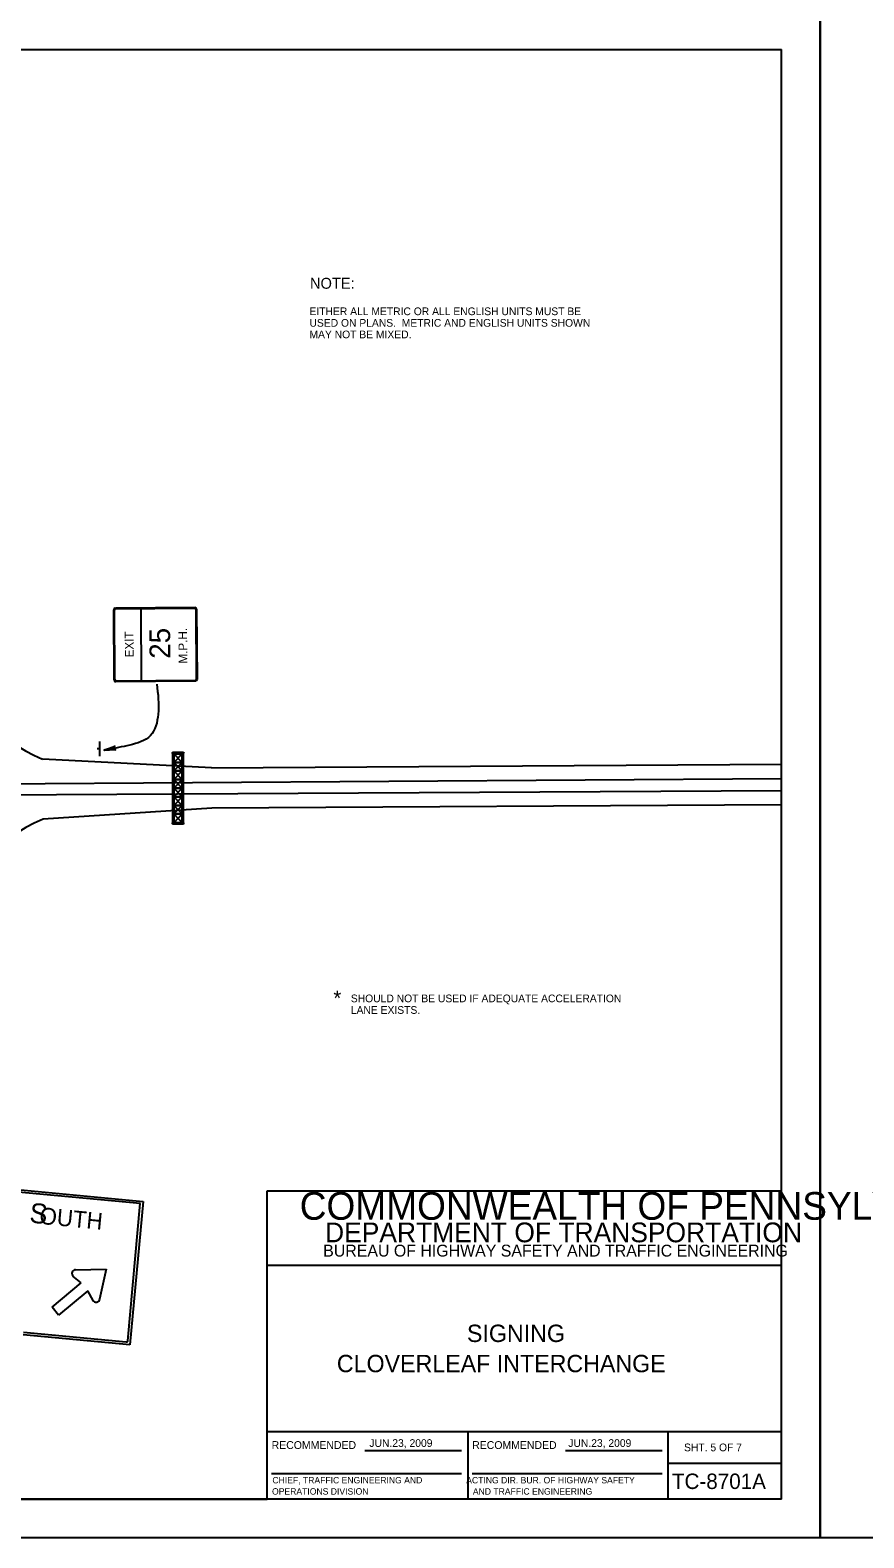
# Model space of a CAD drawing. Extents: x 640994 to 644422, y 298458 to 299646.
# Drawn here: x 641528 to 641852, y 298458 to 299044 of the extents above; entities that cross this region are included whole.
import ezdxf

# ---------------------------------------------------------------- set-up
doc = ezdxf.new("R2010")
doc.units = 0
for name, color, linetype in [('1', 7, 'Continuous'), ('2', 7, 'Continuous'), ('PLT-BNDY', 7, 'Continuous'), ('XCS-GRID-MIN', 7, 'Continuous')]:
    doc.layers.add(name, color=color, linetype=linetype)

msp = doc.modelspace()

# ---------------------------------------------------------------- linework, layer by layer
at = {"layer": '1'}
for p, q in [((641034.31, 299036.63), (641820.31, 299036.63)), ((641820.31, 298472.63), (641820.31, 299036.63)), ((641620.31, 298472.63), (641620.31, 298592.63)), ((641620.31, 298592.63), (641820.31, 298592.63)), ((641820.31, 298563.63), (641620.31, 298563.63)), ((641620.31, 298499), (641820.31, 298499)), ((641698.31, 298499), (641698.31, 298472.63)), ((641776.19, 298472.63), (641776.19, 298499)), ((641658.24, 298491.57), (641695.87, 298491.57)), ((641736.24, 298491.57), (641773.87, 298491.57)), ((641621.99, 298482.68), (641695.87, 298482.68)), ((641699.99, 298482.68), (641773.87, 298482.68)), ((641776.19, 298486.63), (641820.31, 298486.63)), ((641820.31, 298472.63), (641034.31, 298472.63)), ((641034.31, 298472.63), (641620.31, 298472.63))]:
    msp.add_line(p, q, dxfattribs=at)
at = {"layer": '2'}
for p, q in [((641560.69, 298791.38), (641560.56, 298818.63)), ((641560.94, 298791.5), (641560.81, 298818.38)), ((641561.19, 298819.38), (641592.19, 298819.63)), ((641561.31, 298819), (641591.94, 298819.25)), ((641571.31, 298791), (641571.19, 298819.13)), ((641592.56, 298818.63), (641592.69, 298791.75)), ((641592.81, 298818.88), (641593.06, 298791.5)), ((641592.44, 298790.88), (641561.31, 298790.63)), ((641592.19, 298791.13), (641561.56, 298790.88)), ((641555.06, 298764.5), (641554.06, 298764.5)), ((641555.06, 298767.38), (641555.06, 298761.75)), ((641598.56, 298757.13), (641532.94, 298760.5)), ((641583.94, 298762.63), (641587.19, 298759.25)), ((641587.19, 298762.63), (641583.94, 298759.25)), ((641583.94, 298759.25), (641587.19, 298756)), ((641587.19, 298759.25), (641583.94, 298756)), ((641598.56, 298757.13), (641820.31, 298758.53)), ((641820.31, 298752.92), (641403.56, 298750.13)), ((641583.94, 298756), (641587.19, 298752.63)), ((641587.19, 298756), (641583.94, 298752.63)), ((641583.94, 298752.63), (641587.19, 298749.25)), ((641587.19, 298752.63), (641583.94, 298749.25)), ((641403.06, 298746), (641820.31, 298748.39)), ((641583.94, 298749.25), (641587.19, 298745.88)), ((641587.19, 298749.25), (641583.94, 298745.88)), ((641583.94, 298745.88), (641587.19, 298742.5)), ((641587.19, 298745.88), (641583.94, 298742.5)), ((641598.69, 298741.5), (641533.06, 298737.25)), ((641583.94, 298742.5), (641587.19, 298739.25)), ((641587.19, 298742.5), (641583.94, 298739.25)), ((641820.31, 298742.77), (641598.69, 298741.5)), ((641583.94, 298739.25), (641587.19, 298735.75)), ((641587.19, 298739.25), (641583.94, 298735.75)), ((641587.19, 298735.75), (641587.19, 298739.25)), ((641482.95, 298596.91), (641572.07, 298588.42)), ((641566.07, 298534.29), (641570.89, 298587.75)), ((641572.07, 298588.42), (641566.82, 298532.67)), ((641547.95, 298556.79), (641544.7, 298559.42)), ((641545.7, 298561.92), (641557.57, 298562.17)), ((641557.57, 298562.17), (641555.07, 298550.42)), ((641536.57, 298547.42), (641547.95, 298556.79)), ((641550.45, 298553.67), (641539.07, 298544.29)), ((641552.57, 298549.92), (641550.45, 298553.67)), ((641539.07, 298544.29), (641536.57, 298547.42)), ((641566.82, 298532.67), (641525.37, 298536.61)), ((641525.47, 298537.63), (641565.45, 298533.92))]:
    msp.add_line(p, q, dxfattribs=at)
for points in [[(641561.03, 298764.34), (641560.78, 298764.59), (641556.9, 298764.09), (641561.03, 298764.34), (641561.28, 298764.21), (641556.9, 298764.09), (641560.78, 298764.96), (641560.78, 298765.21), (641556.9, 298764.09), (641561.03, 298765.59), (641560.78, 298765.21)], [(641587.19, 298763.13), (641583.94, 298763.13)], [(641583.44, 298762.63), (641583.44, 298735.75)], [(641583.94, 298735.75), (641587.19, 298735.75), (641587.19, 298762.63), (641583.94, 298762.63), (641583.94, 298735.75)], [(641587.69, 298735.75), (641587.69, 298762.63)], [(641583.94, 298735.38), (641587.19, 298735.38)], [(641570.89, 298587.75), (641484.32, 298595.67)]]:
    msp.add_lwpolyline(points, dxfattribs=at)
for points in [[(641583.94, 298759.25), (641583.94, 298762.63), (641587.19, 298762.63), (641587.19, 298759.25)], [(641583.94, 298756), (641583.94, 298759.25), (641587.19, 298759.25), (641587.19, 298756)], [(641583.94, 298752.63), (641583.94, 298756), (641587.19, 298756), (641587.19, 298752.63)], [(641583.94, 298749.25), (641583.94, 298752.63), (641587.19, 298752.63), (641587.19, 298749.25)], [(641583.94, 298745.88), (641583.94, 298749.25), (641587.19, 298749.25), (641587.19, 298745.88)], [(641583.94, 298742.5), (641583.94, 298745.88), (641587.19, 298745.88), (641587.19, 298742.5)], [(641583.94, 298739.25), (641583.94, 298742.5), (641587.19, 298742.5), (641587.19, 298739.25)], [(641583.94, 298735.75), (641583.94, 298739.25), (641587.19, 298739.25), (641587.19, 298735.75)]]:
    msp.add_lwpolyline(points, close=True, dxfattribs=at)
for centre in [(641583.7, 298762.91), (641587.48, 298762.91), (641583.7, 298735.61), (641587.48, 298735.61)]:
    msp.add_circle(centre, 0.301, dxfattribs=at)
for centre, radius, start, end in [((641555.3, 298815.87), 59.66, 191.54204, 247.96006), ((641556.17, 298682.23), 59.66, 112.7883, 169.20632), ((641570.38, 298587.12), 0.528, 354.14399, 84.50768), ((641545.72, 298560.49), 1.4, 89.42516, 230.09068), ((641553.72, 298550.69), 1.4, 207.81363, 351.72026), ((641565.52, 298534.36), 0.528, 264.80557, 354.95755)]:
    msp.add_arc(centre, radius, start, end, dxfattribs=at)
for centre, major_axis, start_param, end_param in [((641561.19, 298818.62), (0.005, -0.717), 3.141593, 4.712389), ((641561.38, 298818.41), (0.004, -0.657), 3.141593, 4.712389), ((641591.98, 298818.61), (-0.004, 0.657), 4.712389, 6.283185), ((641592.17, 298818.82), (-0.005, 0.717), 4.712389, 6.283185), ((641561.37, 298791.37), (0.005, -0.717), 4.712389, 6.283185), ((641561.56, 298791.58), (0.004, -0.657), 4.712389, 6.283185), ((641592.15, 298791.78), (-0.004, 0.657), 3.141593, 4.712389), ((641592.34, 298791.58), (0.005, -0.717), 0, 1.570796)]:
    msp.add_ellipse(centre, major_axis=major_axis, ratio=0.9, start_param=start_param, end_param=end_param, dxfattribs=at)
msp.add_spline([(641577.3, 298789.76), (641577.85, 298777.96), (641574.82, 298769.72), (641566.77, 298766), (641558.15, 298764.3)], degree=3, dxfattribs=at)
at = {"layer": 'XCS-GRID-MIN'}
for points in [[(640994.31, 299051.63), (641835.31, 299051.63), (641835.31, 298457.63), (640994.31, 298457.63)], [(641835.31, 299051.63), (642676.31, 299051.63), (642676.31, 298457.63), (641835.31, 298457.63)]]:
    msp.add_lwpolyline(points, close=True, dxfattribs=at)

# ---------------------------------------------------------------- texts
at = {"layer": '1'}
for s, height, p in [('COMMONWEALTH OF PENNSYLVANIA', 10.7828, (641632.9, 298581.36)), ('DEPARTMENT OF TRANSPORTATION', 7.6837, (641642.76, 298572.61)), ('BUREAU OF HIGHWAY SAFETY AND TRAFFIC ENGINEERING', 4.6253, (641642.04, 298567.04)), ('SIGNING', 6.75, (641697.96, 298533.81)), ('CLOVERLEAF INTERCHANGE', 6.75, (641647.36, 298522.06)), ('RECOMMENDED', 3.048, (641621.99, 298492.2)), ('RECOMMENDED', 3.048, (641699.99, 298492.2)), ('SHT. 5 OF 7', 3, (641782.4, 298491.31)), ('TC-8701A', 6, (641777.68, 298476.63))]:
    msp.add_text(s, height=height, dxfattribs=at).set_placement(p)
at = {"layer": '2'}
for s, height, p in [('NOTE:', 4.25, (641636.91, 298943.53)), ('EITHER ALL METRIC OR ALL ENGLISH UNITS MUST BE', 3, (641636.7, 298933.26)), ('USED ON PLANS.  METRIC AND ENGLISH UNITS SHOWN', 3, (641636.7, 298928.76)), ('MAY NOT BE MIXED.', 3, (641636.7, 298924.26)), ('*', 5.85, (641646.02, 298664.66)), ('SHOULD NOT BE USED IF ADEQUATE ACCELERATION', 3, (641652.79, 298665.97)), ('LANE EXISTS.', 3, (641652.79, 298661.47)), ('JUN.23, 2009', 3, (641660.01, 298493))]:
    msp.add_text(s, height=height, dxfattribs=at).set_placement(p)
for s, height, rotation, p in [('EXIT', 3.387, 90.3745, (641568.31, 298800.13)), ('25', 8.061, 90.37458, (641582.56, 298799.63)), ('M.P.H.', 3.387, 90.37456, (641589.19, 298797.75)), ('35', 0.0217, 90, (641572.56, 298800.88)), ('S', 7.75, 354.58165, (641527.57, 298580.29)), ('OUTH', 6.5, 354.56831, (641531.45, 298579.79)), ('JUN.23, 2009', 3, 360, (641737.36, 298493))]:
    msp.add_text(s, height=height, rotation=rotation, dxfattribs=at).set_placement(p)
at = {"layer": 'PLT-BNDY'}
for s, p in [('OPERATIONS DIVISION', (641622.14, 298474.44)), ('CHIEF, TRAFFIC ENGINEERING AND', (641622.28, 298478.81)), ('  ACTING DIR. BUR. OF HIGHWAY SAFETY', (641695.81, 298478.8)), ('  ACTING DIR. BUR. OF HIGHWAY SAFETY', (641695.81, 298478.8))]:
    msp.add_text(s, height=2.5, dxfattribs=at).set_placement(p)
msp.add_text('AND TRAFFIC ENGINEERING', height=2.5, rotation=360, dxfattribs=at).set_placement((641700.25, 298474.43))
msp.add_text('AND TRAFFIC ENGINEERING', height=2.5, rotation=360, dxfattribs=at).set_placement((641700.25, 298474.43))

doc.saveas('drawing.dxf')
